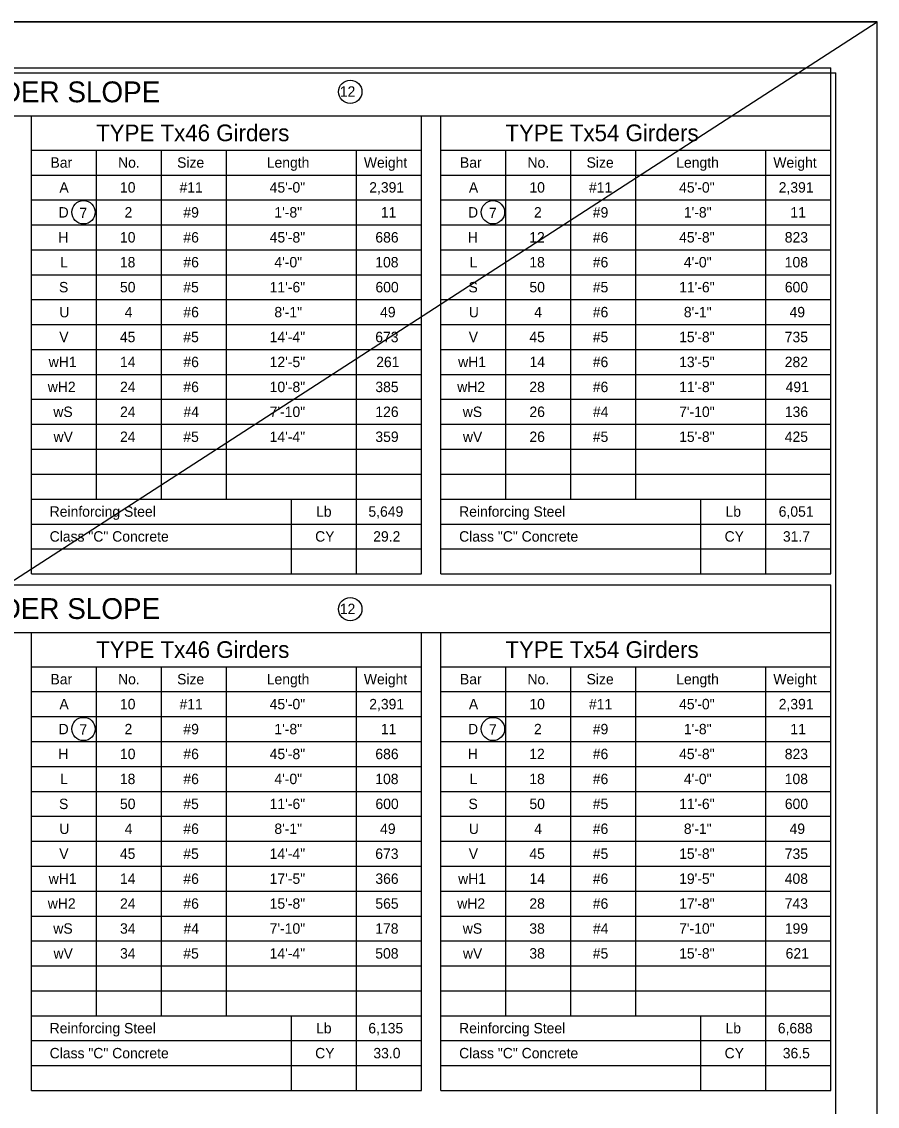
# Model space of a CAD drawing. Extents: x 926 to 1074, y 990 to 1081.
# Drawn here: x 1023.65 to 1034, y 1031.88 to 1045 of the extents above; entities that cross this region are included whole.
import ezdxf

# ---------------------------------------------------------------- set-up
doc = ezdxf.new("R2010")
doc.units = 0
for name, color, linetype in [('BORD_lines_major', 7, 'Continuous'), ('D_BATCH_PLOT', 7, 'Continuous'), ('D_SHEET', 7, 'Continuous'), ('Working Level 1', 7, 'Continuous')]:
    doc.layers.add(name, color=color, linetype=linetype)

msp = doc.modelspace()

# ---------------------------------------------------------------- linework, layer by layer
at = {"layer": 'BORD_lines_major'}
for p in [(1002.413, 1044.382), (1033.5, 1023.5)]:
    msp.add_line(p, (1033.5, 1044.382), dxfattribs=at)
at = {"layer": 'D_BATCH_PLOT'}
msp.add_lwpolyline([(1000, 1023), (1034, 1023), (1034, 1045), (1000, 1045)], close=True, dxfattribs=at)
at = {"layer": 'D_SHEET'}
for p in [(1000, 1045), (1034, 1023)]:
    msp.add_line(p, (1034, 1045), dxfattribs=at)
at = {"layer": 'Working Level 1'}
for p, q in [((1000, 1023), (1034, 1045)), ((1008.919, 1044.44), (1033.44, 1044.44)), ((1033.44, 1038.319), (1033.44, 1044.44)), ((1008.919, 1043.862), (1033.44, 1043.862)), ((1023.772, 1038.319), (1023.772, 1043.862)), ((1028.489, 1038.319), (1028.489, 1043.862)), ((1028.722, 1038.319), (1028.722, 1043.862)), ((1023.772, 1043.447), (1028.489, 1043.447)), ((1024.558, 1039.224), (1024.558, 1043.447)), ((1025.344, 1039.224), (1025.344, 1043.447)), ((1026.13, 1039.224), (1026.13, 1043.447)), ((1027.703, 1038.319), (1027.703, 1043.447)), ((1028.722, 1043.447), (1033.44, 1043.447)), ((1029.509, 1039.224), (1029.509, 1043.447)), ((1030.295, 1039.224), (1030.295, 1043.447)), ((1031.081, 1039.224), (1031.081, 1043.447)), ((1032.654, 1038.319), (1032.654, 1043.447)), ((1023.772, 1043.145), (1028.489, 1043.145)), ((1025.344, 1039.224), (1025.344, 1043.145)), ((1026.13, 1039.224), (1026.13, 1043.145)), ((1028.722, 1043.145), (1033.44, 1043.145)), ((1030.295, 1039.224), (1030.295, 1043.145)), ((1031.081, 1039.224), (1031.081, 1043.145)), ((1023.772, 1042.844), (1028.489, 1042.844)), ((1028.722, 1042.844), (1033.44, 1042.844)), ((1023.772, 1042.542), (1028.489, 1042.542)), ((1028.722, 1042.542), (1033.44, 1042.542)), ((1023.772, 1042.24), (1028.489, 1042.24)), ((1028.722, 1042.24), (1033.44, 1042.24)), ((1023.772, 1041.939), (1028.489, 1041.939)), ((1028.722, 1041.939), (1033.44, 1041.939)), ((1023.772, 1041.637), (1028.489, 1041.637)), ((1028.722, 1041.637), (1033.44, 1041.637)), ((1023.772, 1041.336), (1028.489, 1041.336)), ((1028.722, 1041.336), (1033.44, 1041.336)), ((1023.772, 1041.034), (1028.489, 1041.034)), ((1028.722, 1041.034), (1033.44, 1041.034)), ((1023.772, 1040.732), (1028.489, 1040.732)), ((1028.722, 1040.732), (1033.44, 1040.732)), ((1023.772, 1040.431), (1028.489, 1040.431)), ((1028.722, 1040.431), (1033.44, 1040.431)), ((1023.772, 1040.129), (1028.489, 1040.129)), ((1028.722, 1040.129), (1033.44, 1040.129)), ((1023.772, 1039.827), (1028.489, 1039.827)), ((1028.722, 1039.827), (1033.44, 1039.827)), ((1023.772, 1039.526), (1028.489, 1039.526)), ((1028.722, 1039.526), (1033.44, 1039.526)), ((1023.772, 1039.224), (1028.489, 1039.224)), ((1026.917, 1038.319), (1026.917, 1039.224)), ((1028.722, 1039.224), (1033.44, 1039.224)), ((1031.867, 1038.319), (1031.867, 1039.224)), ((1023.772, 1038.922), (1028.489, 1038.922)), ((1028.722, 1038.922), (1033.44, 1038.922)), ((1023.772, 1038.621), (1028.489, 1038.621)), ((1028.722, 1038.621), (1033.44, 1038.621)), ((1023.772, 1038.319), (1028.489, 1038.319)), ((1028.722, 1038.319), (1033.44, 1038.319)), ((1008.919, 1038.188), (1033.44, 1038.188)), ((1033.44, 1032.068), (1033.44, 1038.188)), ((1008.919, 1037.61), (1033.44, 1037.61)), ((1023.772, 1032.068), (1023.772, 1037.61)), ((1028.489, 1032.068), (1028.489, 1037.61)), ((1028.722, 1032.068), (1028.722, 1037.61)), ((1023.772, 1037.195), (1028.489, 1037.195)), ((1024.558, 1032.972), (1024.558, 1037.195)), ((1025.344, 1032.972), (1025.344, 1037.195)), ((1026.13, 1032.972), (1026.13, 1037.195)), ((1027.703, 1032.068), (1027.703, 1037.195)), ((1028.722, 1037.195), (1033.44, 1037.195)), ((1029.509, 1032.972), (1029.509, 1037.195)), ((1030.295, 1032.972), (1030.295, 1037.195)), ((1031.081, 1032.972), (1031.081, 1037.195)), ((1032.654, 1032.068), (1032.654, 1037.195)), ((1023.772, 1036.894), (1028.489, 1036.894)), ((1025.344, 1032.972), (1025.344, 1036.894)), ((1026.13, 1032.972), (1026.13, 1036.894)), ((1028.722, 1036.894), (1033.44, 1036.894)), ((1030.295, 1032.972), (1030.295, 1036.894)), ((1031.081, 1032.972), (1031.081, 1036.894)), ((1023.772, 1036.592), (1028.489, 1036.592)), ((1028.722, 1036.592), (1033.44, 1036.592)), ((1023.772, 1036.291), (1028.489, 1036.291)), ((1028.722, 1036.291), (1033.44, 1036.291)), ((1023.772, 1035.989), (1028.489, 1035.989)), ((1028.722, 1035.989), (1033.44, 1035.989)), ((1023.772, 1035.687), (1028.489, 1035.687)), ((1028.722, 1035.687), (1033.44, 1035.687)), ((1023.772, 1035.386), (1028.489, 1035.386)), ((1028.722, 1035.386), (1033.44, 1035.386)), ((1023.772, 1035.084), (1028.489, 1035.084)), ((1028.722, 1035.084), (1033.44, 1035.084)), ((1023.772, 1034.782), (1028.489, 1034.782)), ((1028.722, 1034.782), (1033.44, 1034.782)), ((1023.772, 1034.481), (1028.489, 1034.481)), ((1028.722, 1034.481), (1033.44, 1034.481)), ((1023.772, 1034.179), (1028.489, 1034.179)), ((1028.722, 1034.179), (1033.44, 1034.179)), ((1023.772, 1033.877), (1028.489, 1033.877)), ((1028.722, 1033.877), (1033.44, 1033.877)), ((1023.772, 1033.576), (1028.489, 1033.576)), ((1028.722, 1033.576), (1033.44, 1033.576)), ((1023.772, 1033.274), (1028.489, 1033.274)), ((1028.722, 1033.274), (1033.44, 1033.274)), ((1023.772, 1032.972), (1028.489, 1032.972)), ((1026.917, 1032.068), (1026.917, 1032.972)), ((1028.722, 1032.972), (1033.44, 1032.972)), ((1031.867, 1032.068), (1031.867, 1032.972)), ((1023.772, 1032.671), (1028.489, 1032.671)), ((1028.722, 1032.671), (1033.44, 1032.671)), ((1023.772, 1032.369), (1028.489, 1032.369)), ((1028.722, 1032.369), (1033.44, 1032.369)), ((1023.772, 1032.068), (1028.489, 1032.068)), ((1028.722, 1032.068), (1033.44, 1032.068))]:
    msp.add_line(p, q, dxfattribs=at)
for centre in [(1027.628, 1044.152), (1024.402, 1042.694), (1029.353, 1042.694), (1027.628, 1037.892), (1024.402, 1036.442), (1029.353, 1036.442)]:
    msp.add_circle(centre, 0.141, dxfattribs=at)

# ---------------------------------------------------------------- texts
for s, height, p in [('TABLES OF ESTIMATED QUANTITIES WITH 2:1 HEADER SLOPE', 0.252, (1015.107, 1044.025)), ('12', 0.126, (1027.501, 1044.092)), ('TYPE Tx46 Girders ', 0.2016, (1024.554, 1043.554)), ('TYPE Tx54 Girders ', 0.2016, (1029.503, 1043.554)), ('Bar', 0.126, (1024.003, 1043.233)), ('No.', 0.126, (1024.82, 1043.233)), ('Size', 0.126, (1025.534, 1043.233)), ('Length', 0.126, (1026.618, 1043.233)), ('Weight', 0.126, (1027.792, 1043.233)), ('Bar', 0.126, (1028.954, 1043.233)), ('No.', 0.126, (1029.77, 1043.233)), ('Size', 0.126, (1030.485, 1043.233)), ('Length', 0.126, (1031.569, 1043.233)), ('Weight', 0.126, (1032.743, 1043.233)), ('A', 0.126, (1024.111, 1042.932)), ('10', 0.126, (1024.843, 1042.932)), ('#11', 0.126, (1025.563, 1042.932)), ('45\'-0"', 0.126, (1026.653, 1042.932)), ('2,391', 0.126, (1027.857, 1042.932)), ('A', 0.126, (1029.062, 1042.932)), ('10', 0.126, (1029.794, 1042.932)), ('#11', 0.126, (1030.514, 1042.932)), ('45\'-0"', 0.126, (1031.604, 1042.932)), ('2,391', 0.126, (1032.808, 1042.932)), ('D', 0.126, (1024.101, 1042.63)), ('7', 0.126, (1024.353, 1042.623)), ('2', 0.126, (1024.898, 1042.63)), ('#9', 0.126, (1025.61, 1042.63)), ('1\'-8"', 0.126, (1026.71, 1042.63)), ('11', 0.126, (1027.998, 1042.63)), ('D', 0.126, (1029.052, 1042.63)), ('7', 0.126, (1029.304, 1042.623)), ('2', 0.126, (1029.849, 1042.63)), ('#9', 0.126, (1030.56, 1042.63)), ('1\'-8"', 0.126, (1031.661, 1042.63)), ('11', 0.126, (1032.949, 1042.63)), ('H', 0.126, (1024.098, 1042.328)), ('10', 0.126, (1024.843, 1042.328)), ('#6', 0.126, (1025.61, 1042.328)), ('45\'-8"', 0.126, (1026.653, 1042.328)), ('686', 0.126, (1027.931, 1042.328)), ('H', 0.126, (1029.048, 1042.328)), ('12', 0.126, (1029.792, 1042.328)), ('#6', 0.126, (1030.56, 1042.328)), ('45\'-8"', 0.126, (1031.604, 1042.328)), ('823', 0.126, (1032.881, 1042.328)), ('L', 0.126, (1024.12, 1042.027)), ('18', 0.126, (1024.842, 1042.027)), ('#6', 0.126, (1025.61, 1042.027)), ('4\'-0"', 0.126, (1026.71, 1042.027)), ('108', 0.126, (1027.93, 1042.027)), ('L', 0.126, (1029.071, 1042.027)), ('18', 0.126, (1029.793, 1042.027)), ('#6', 0.126, (1030.56, 1042.027)), ('4\'-0"', 0.126, (1031.661, 1042.027)), ('108', 0.126, (1032.881, 1042.027)), ('S', 0.126, (1024.106, 1041.725)), ('50', 0.126, (1024.843, 1041.725)), ('#5', 0.126, (1025.609, 1041.725)), ('11\'-6"', 0.126, (1026.653, 1041.725)), ('600', 0.126, (1027.932, 1041.725)), ('S', 0.126, (1029.057, 1041.725)), ('50', 0.126, (1029.794, 1041.725)), ('#5', 0.126, (1030.56, 1041.725)), ('11\'-6"', 0.126, (1031.604, 1041.725)), ('600', 0.126, (1032.882, 1041.725)), ('U', 0.126, (1024.11, 1041.423)), ('4', 0.126, (1024.901, 1041.423)), ('#6', 0.126, (1025.61, 1041.423)), ('8\'-1"', 0.126, (1026.71, 1041.423)), ('49', 0.126, (1027.988, 1041.423)), ('U', 0.126, (1029.061, 1041.423)), ('4', 0.126, (1029.852, 1041.423)), ('#6', 0.126, (1030.56, 1041.423)), ('8\'-1"', 0.126, (1031.661, 1041.423)), ('49', 0.126, (1032.939, 1041.423)), ('V', 0.126, (1024.109, 1041.122)), ('45', 0.126, (1024.842, 1041.122)), ('#5', 0.126, (1025.609, 1041.122)), ('14\'-4"', 0.126, (1026.653, 1041.122)), ('673', 0.126, (1027.93, 1041.122)), ('V', 0.126, (1029.06, 1041.122)), ('45', 0.126, (1029.793, 1041.122)), ('#5', 0.126, (1030.56, 1041.122)), ('15\'-8"', 0.126, (1031.604, 1041.122)), ('735', 0.126, (1032.881, 1041.122)), ('wH1', 0.126, (1023.981, 1040.82)), ('14', 0.126, (1024.844, 1040.82)), ('#6', 0.126, (1025.61, 1040.82)), ('12\'-5"', 0.126, (1026.653, 1040.82)), ('261', 0.126, (1027.941, 1040.82)), ('wH1', 0.126, (1028.932, 1040.82)), ('14', 0.126, (1029.795, 1040.82)), ('#6', 0.126, (1030.56, 1040.82)), ('13\'-5"', 0.126, (1031.604, 1040.82)), ('282', 0.126, (1032.881, 1040.82)), ('wH2', 0.126, (1023.97, 1040.518)), ('24', 0.126, (1024.844, 1040.518)), ('#6', 0.126, (1025.61, 1040.518)), ('10\'-8"', 0.126, (1026.653, 1040.518)), ('385', 0.126, (1027.931, 1040.518)), ('wH2', 0.126, (1028.921, 1040.518)), ('28', 0.126, (1029.793, 1040.518)), ('#6', 0.126, (1030.56, 1040.518)), ('11\'-8"', 0.126, (1031.604, 1040.518)), ('491', 0.126, (1032.892, 1040.518)), ('wS', 0.126, (1024.037, 1040.217)), ('24', 0.126, (1024.844, 1040.217)), ('#4', 0.126, (1025.611, 1040.217)), ('7\'-10"', 0.126, (1026.653, 1040.217)), ('126', 0.126, (1027.931, 1040.217)), ('wS', 0.126, (1028.988, 1040.217)), ('26', 0.126, (1029.794, 1040.217)), ('#4', 0.126, (1030.562, 1040.217)), ('7\'-10"', 0.126, (1031.604, 1040.217)), ('136', 0.126, (1032.882, 1040.217)), ('wV', 0.126, (1024.04, 1039.915)), ('24', 0.126, (1024.844, 1039.915)), ('#5', 0.126, (1025.609, 1039.915)), ('14\'-4"', 0.126, (1026.653, 1039.915)), ('359', 0.126, (1027.931, 1039.915)), ('wV', 0.126, (1028.99, 1039.915)), ('26', 0.126, (1029.794, 1039.915)), ('#5', 0.126, (1030.56, 1039.915)), ('15\'-8"', 0.126, (1031.604, 1039.915)), ('425', 0.126, (1032.881, 1039.915)), ('Reinforcing Steel', 0.126, (1023.993, 1039.01)), ('Lb', 0.126, (1027.214, 1039.01)), ('5,649', 0.126, (1027.847, 1039.01)), ('Reinforcing Steel', 0.126, (1028.944, 1039.01)), ('Lb', 0.126, (1032.165, 1039.01)), ('6,051', 0.126, (1032.808, 1039.01)), ('Class "C" Concrete', 0.126, (1023.993, 1038.709)), ('CY', 0.126, (1027.203, 1038.709)), ('29.2', 0.126, (1027.905, 1038.709)), ('Class "C" Concrete', 0.126, (1028.944, 1038.709)), ('CY', 0.126, (1032.154, 1038.709)), ('31.7', 0.126, (1032.859, 1038.709)), ('TABLES OF ESTIMATED QUANTITIES WITH 3:1 HEADER SLOPE', 0.252, (1015.106, 1037.773)), ('12', 0.126, (1027.501, 1037.832)), ('TYPE Tx46 Girders ', 0.2016, (1024.554, 1037.302)), ('TYPE Tx54 Girders ', 0.2016, (1029.503, 1037.302)), ('Bar', 0.126, (1024.003, 1036.982)), ('No.', 0.126, (1024.82, 1036.982)), ('Size', 0.126, (1025.534, 1036.982)), ('Length', 0.126, (1026.618, 1036.982)), ('Weight', 0.126, (1027.792, 1036.982)), ('Bar', 0.126, (1028.954, 1036.982)), ('No.', 0.126, (1029.77, 1036.982)), ('Size', 0.126, (1030.485, 1036.982)), ('Length', 0.126, (1031.569, 1036.982)), ('Weight', 0.126, (1032.743, 1036.982)), ('A', 0.126, (1024.111, 1036.68)), ('10', 0.126, (1024.843, 1036.68)), ('#11', 0.126, (1025.563, 1036.68)), ('45\'-0"', 0.126, (1026.653, 1036.68)), ('2,391', 0.126, (1027.857, 1036.68)), ('A', 0.126, (1029.062, 1036.68)), ('10', 0.126, (1029.794, 1036.68)), ('#11', 0.126, (1030.514, 1036.68)), ('45\'-0"', 0.126, (1031.604, 1036.68)), ('2,391', 0.126, (1032.808, 1036.68)), ('D', 0.126, (1024.101, 1036.378)), ('7', 0.126, (1024.353, 1036.372)), ('2', 0.126, (1024.898, 1036.378)), ('#9', 0.126, (1025.61, 1036.378)), ('1\'-8"', 0.126, (1026.71, 1036.378)), ('11', 0.126, (1027.998, 1036.378)), ('D', 0.126, (1029.052, 1036.378)), ('7', 0.126, (1029.304, 1036.372)), ('2', 0.126, (1029.849, 1036.378)), ('#9', 0.126, (1030.56, 1036.378)), ('1\'-8"', 0.126, (1031.661, 1036.378)), ('11', 0.126, (1032.949, 1036.378)), ('H', 0.126, (1024.098, 1036.077)), ('10', 0.126, (1024.843, 1036.077)), ('#6', 0.126, (1025.61, 1036.077)), ('45\'-8"', 0.126, (1026.653, 1036.077)), ('686', 0.126, (1027.931, 1036.077)), ('H', 0.126, (1029.048, 1036.077)), ('12', 0.126, (1029.792, 1036.077)), ('#6', 0.126, (1030.56, 1036.077)), ('45\'-8"', 0.126, (1031.604, 1036.077)), ('823', 0.126, (1032.881, 1036.077)), ('L', 0.126, (1024.12, 1035.775)), ('18', 0.126, (1024.842, 1035.775)), ('#6', 0.126, (1025.61, 1035.775)), ('4\'-0"', 0.126, (1026.71, 1035.775)), ('108', 0.126, (1027.93, 1035.775)), ('L', 0.126, (1029.071, 1035.775)), ('18', 0.126, (1029.793, 1035.775)), ('#6', 0.126, (1030.56, 1035.775)), ('4\'-0"', 0.126, (1031.661, 1035.775)), ('108', 0.126, (1032.881, 1035.775)), ('S', 0.126, (1024.106, 1035.473)), ('50', 0.126, (1024.843, 1035.473)), ('#5', 0.126, (1025.609, 1035.473)), ('11\'-6"', 0.126, (1026.653, 1035.473)), ('600', 0.126, (1027.932, 1035.473)), ('S', 0.126, (1029.057, 1035.473)), ('50', 0.126, (1029.794, 1035.473)), ('#5', 0.126, (1030.56, 1035.473)), ('11\'-6"', 0.126, (1031.604, 1035.473)), ('600', 0.126, (1032.882, 1035.473)), ('#6', 0.126, (1025.61, 1035.172)), ('8\'-1"', 0.126, (1026.71, 1035.172)), ('49', 0.126, (1027.988, 1035.172)), ('#6', 0.126, (1030.56, 1035.172)), ('8\'-1"', 0.126, (1031.661, 1035.172)), ('49', 0.126, (1032.939, 1035.172)), ('U', 0.126, (1024.11, 1035.172)), ('4', 0.126, (1024.901, 1035.172)), ('U', 0.126, (1029.061, 1035.172)), ('4', 0.126, (1029.852, 1035.172)), ('V', 0.126, (1024.109, 1034.87)), ('45', 0.126, (1024.842, 1034.87)), ('#5', 0.126, (1025.609, 1034.87)), ('14\'-4"', 0.126, (1026.653, 1034.87)), ('673', 0.126, (1027.93, 1034.87)), ('V', 0.126, (1029.06, 1034.87)), ('45', 0.126, (1029.793, 1034.87)), ('#5', 0.126, (1030.56, 1034.87)), ('15\'-8"', 0.126, (1031.604, 1034.87)), ('735', 0.126, (1032.881, 1034.87)), ('wH1', 0.126, (1023.981, 1034.568)), ('14', 0.126, (1024.844, 1034.568)), ('#6', 0.126, (1025.61, 1034.568)), ('17\'-5"', 0.126, (1026.653, 1034.568)), ('366', 0.126, (1027.931, 1034.568)), ('wH1', 0.126, (1028.932, 1034.568)), ('14', 0.126, (1029.795, 1034.568)), ('#6', 0.126, (1030.56, 1034.568)), ('19\'-5"', 0.126, (1031.604, 1034.568)), ('408', 0.126, (1032.881, 1034.568)), ('wH2', 0.126, (1023.97, 1034.267)), ('24', 0.126, (1024.844, 1034.267)), ('#6', 0.126, (1025.61, 1034.267)), ('15\'-8"', 0.126, (1026.653, 1034.267)), ('565', 0.126, (1027.931, 1034.267)), ('wH2', 0.126, (1028.921, 1034.267)), ('28', 0.126, (1029.793, 1034.267)), ('#6', 0.126, (1030.56, 1034.267)), ('17\'-8"', 0.126, (1031.604, 1034.267)), ('743', 0.126, (1032.881, 1034.267)), ('wS', 0.126, (1024.037, 1033.965)), ('34', 0.126, (1024.844, 1033.965)), ('#4', 0.126, (1025.611, 1033.965)), ('7\'-10"', 0.126, (1026.653, 1033.965)), ('178', 0.126, (1027.93, 1033.965)), ('wS', 0.126, (1028.988, 1033.965)), ('38', 0.126, (1029.793, 1033.965)), ('#4', 0.126, (1030.562, 1033.965)), ('7\'-10"', 0.126, (1031.604, 1033.965)), ('199', 0.126, (1032.882, 1033.965)), ('wV', 0.126, (1024.04, 1033.664)), ('34', 0.126, (1024.844, 1033.664)), ('#5', 0.126, (1025.609, 1033.664)), ('14\'-4"', 0.126, (1026.653, 1033.664)), ('508', 0.126, (1027.93, 1033.664)), ('wV', 0.126, (1028.99, 1033.664)), ('38', 0.126, (1029.793, 1033.664)), ('#5', 0.126, (1030.56, 1033.664)), ('15\'-8"', 0.126, (1031.604, 1033.664)), ('621', 0.126, (1032.892, 1033.664)), ('Reinforcing Steel', 0.126, (1023.993, 1032.759)), ('Lb', 0.126, (1027.214, 1032.759)), ('6,135', 0.126, (1027.846, 1032.759)), ('Reinforcing Steel', 0.126, (1028.944, 1032.759)), ('Lb', 0.126, (1032.165, 1032.759)), ('6,688', 0.126, (1032.797, 1032.759)), ('Class "C" Concrete', 0.126, (1023.993, 1032.457)), ('CY', 0.126, (1027.203, 1032.457)), ('33.0', 0.126, (1027.907, 1032.457)), ('Class "C" Concrete', 0.126, (1028.944, 1032.457)), ('CY', 0.126, (1032.154, 1032.457)), ('36.5', 0.126, (1032.857, 1032.457))]:
    msp.add_text(s, height=height, dxfattribs=at).set_placement(p)

doc.saveas('drawing.dxf')
